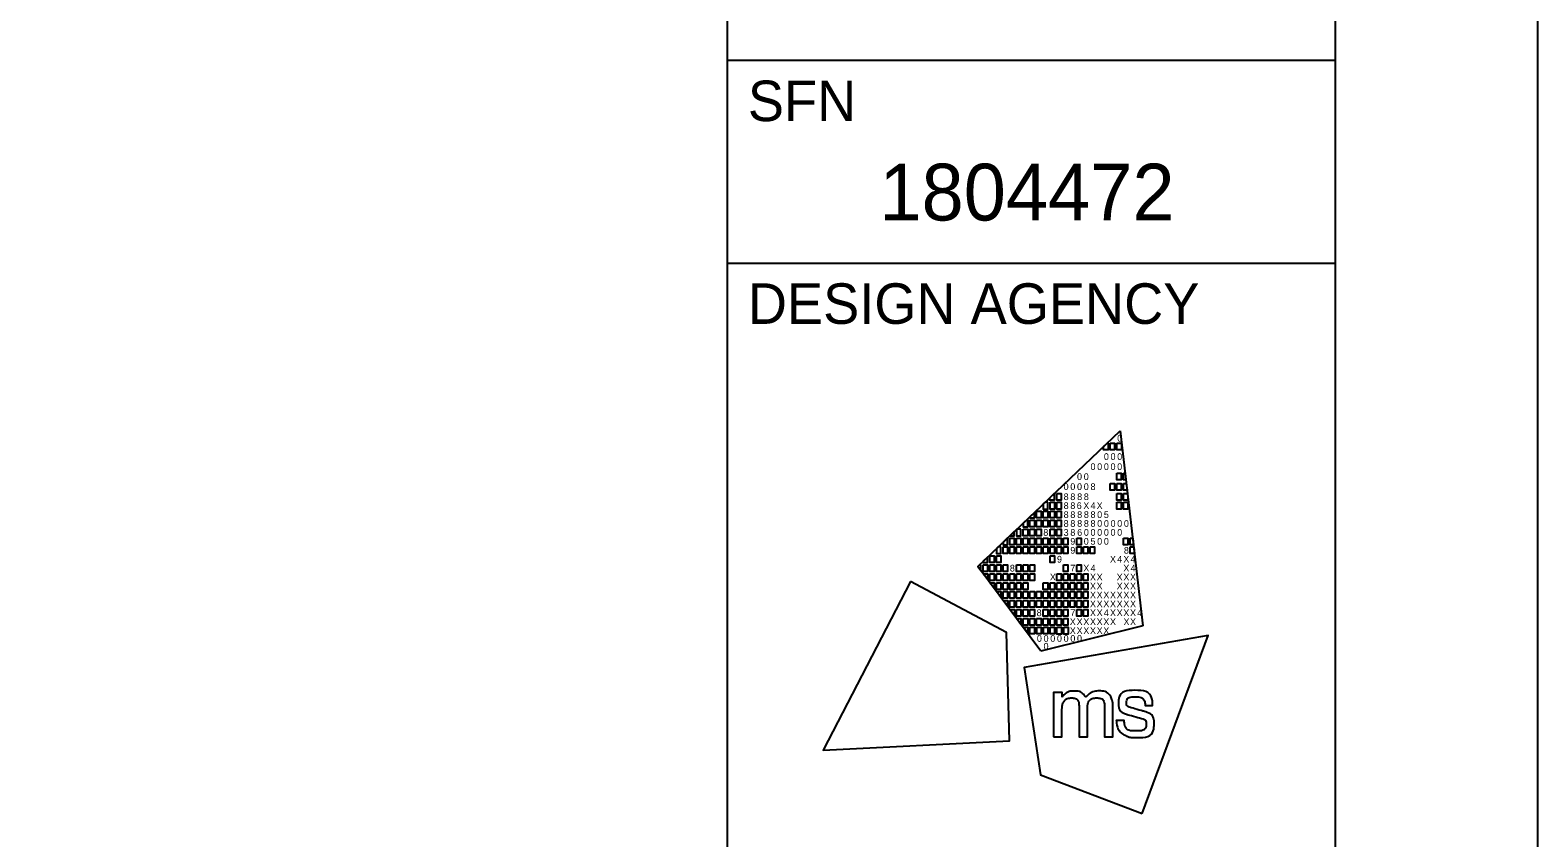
# Model space of a CAD drawing. Extents: x 0 to 34, y 0 to 22.
# Drawn here: x 30.278 to 34, y 3.582 to 5.574 of the extents above; entities that cross this region are included whole.
import ezdxf

# ---------------------------------------------------------------- set-up
doc = ezdxf.new("R2010")
doc.units = 0
for name, color, linetype in [('Default', 7, 'Continuous'), ('SH_Border', 7, 'Continuous'), ('SH_Cut_Line', 7, 'Continuous'), ('SH_Data', 7, 'Continuous')]:
    doc.layers.add(name, color=color, linetype=linetype)

msp = doc.modelspace()

# ---------------------------------------------------------------- linework, layer by layer
at = {"layer": 'Default'}
for p, q in [((32.6176, 4.2519), (32.9688, 4.5861)), ((32.9688, 4.5861), (32.9688, 4.5861)), ((32.9688, 4.5861), (33.0253, 4.1052)), ((32.773, 4.043), (32.6176, 4.2519)), ((33.0253, 4.1052), (32.773, 4.043))]:
    msp.add_line(p, q, dxfattribs=at)
for points in [[(32.9279, 4.5472), (32.9369, 4.5558), (32.939, 4.5558), (32.939, 4.5393), (32.9279, 4.5393)], [(32.9444, 4.5558), (32.9554, 4.5558), (32.9554, 4.5393), (32.9444, 4.5393)], [(32.9609, 4.5558), (32.9719, 4.5558), (32.9719, 4.5393), (32.9609, 4.5393)], [(32.9606, 4.4815), (32.9716, 4.4815), (32.9716, 4.465), (32.9606, 4.465)], [(32.9771, 4.4815), (32.9811, 4.4815), (32.983, 4.465), (32.9771, 4.465)], [(32.7954, 4.4211), (32.8064, 4.4316), (32.8064, 4.4154), (32.7954, 4.4154)], [(32.8123, 4.4319), (32.8233, 4.4319), (32.8233, 4.4154), (32.8123, 4.4154)], [(32.9442, 4.4567), (32.9552, 4.4567), (32.9552, 4.4402), (32.9442, 4.4402)], [(32.9606, 4.4567), (32.9716, 4.4567), (32.9716, 4.4402), (32.9606, 4.4402)], [(32.9606, 4.4319), (32.9716, 4.4319), (32.9716, 4.4154), (32.9606, 4.4154)], [(32.9771, 4.4567), (32.984, 4.4567), (32.9859, 4.4402), (32.9771, 4.4402)], [(32.9771, 4.4319), (32.9869, 4.4319), (32.9881, 4.4218), (32.9881, 4.4154), (32.9771, 4.4154)], [(32.7958, 4.4099), (32.8068, 4.4099), (32.8068, 4.3934), (32.7958, 4.3934)], [(32.8123, 4.4099), (32.8233, 4.4099), (32.8233, 4.3934), (32.8123, 4.3934)], [(32.9606, 4.4099), (32.9716, 4.4099), (32.9716, 4.3934), (32.9606, 4.3934)], [(32.9771, 4.4099), (32.9881, 4.4099), (32.9881, 4.3934), (32.9771, 4.3934)], [(32.7463, 4.3659), (32.7573, 4.3659), (32.7573, 4.3494), (32.7463, 4.3494)], [(32.7628, 4.3879), (32.7738, 4.3879), (32.7738, 4.3714), (32.7628, 4.3714)], [(32.7628, 4.3659), (32.7738, 4.3659), (32.7738, 4.3494), (32.7628, 4.3494)], [(32.7793, 4.3879), (32.7903, 4.3879), (32.7903, 4.3714), (32.7793, 4.3714)], [(32.7793, 4.3659), (32.7903, 4.3659), (32.7903, 4.3494), (32.7793, 4.3494)], [(32.7958, 4.3879), (32.8068, 4.3879), (32.8068, 4.3714), (32.7958, 4.3714)], [(32.7958, 4.3659), (32.8068, 4.3659), (32.8068, 4.3494), (32.7958, 4.3494)], [(32.8123, 4.3879), (32.8233, 4.3879), (32.8233, 4.3714), (32.8123, 4.3714)], [(32.8123, 4.3659), (32.8233, 4.3659), (32.8233, 4.3494), (32.8123, 4.3494)], [(32.6967, 4.3218), (32.7077, 4.3218), (32.7077, 4.3053), (32.6967, 4.3053)], [(32.7132, 4.3218), (32.7242, 4.3218), (32.7242, 4.3053), (32.7132, 4.3053)], [(32.7297, 4.3439), (32.7407, 4.3439), (32.7407, 4.3273), (32.7297, 4.3273)], [(32.7297, 4.3218), (32.7407, 4.3218), (32.7407, 4.3053), (32.7297, 4.3053)], [(32.7463, 4.3439), (32.7573, 4.3439), (32.7573, 4.3273), (32.7463, 4.3273)], [(32.7463, 4.3218), (32.7573, 4.3218), (32.7573, 4.3053), (32.7463, 4.3053)], [(32.7628, 4.3439), (32.7738, 4.3439), (32.7738, 4.3273), (32.7628, 4.3273)], [(32.7628, 4.3218), (32.7738, 4.3218), (32.7738, 4.3053), (32.7628, 4.3053)], [(32.7793, 4.3218), (32.7903, 4.3218), (32.7903, 4.3053), (32.7793, 4.3053)], [(32.7958, 4.3439), (32.8068, 4.3439), (32.8068, 4.3273), (32.7958, 4.3273)], [(32.7958, 4.3218), (32.8068, 4.3218), (32.8068, 4.3053), (32.7958, 4.3053)], [(32.8123, 4.3439), (32.8233, 4.3439), (32.8233, 4.3273), (32.8123, 4.3273)], [(32.8123, 4.3218), (32.8233, 4.3218), (32.8233, 4.3053), (32.8123, 4.3053)], [(32.8288, 4.3218), (32.8398, 4.3218), (32.8398, 4.3053), (32.8288, 4.3053)], [(32.8618, 4.3218), (32.8729, 4.3218), (32.8729, 4.3053), (32.8618, 4.3053)], [(32.9771, 4.3218), (32.9881, 4.3218), (32.9881, 4.3053), (32.9771, 4.3053)], [(32.9936, 4.3218), (32.9999, 4.3218), (33.0018, 4.3053), (32.9936, 4.3053)], [(32.6802, 4.2998), (32.6912, 4.2998), (32.6912, 4.2833), (32.6802, 4.2833)], [(32.6967, 4.2998), (32.7077, 4.2998), (32.7077, 4.2833), (32.6967, 4.2833)], [(32.7132, 4.2998), (32.7242, 4.2998), (32.7242, 4.2833), (32.7132, 4.2833)], [(32.7297, 4.2998), (32.7407, 4.2998), (32.7407, 4.2833), (32.7297, 4.2833)], [(32.7463, 4.2998), (32.7573, 4.2998), (32.7573, 4.2833), (32.7463, 4.2833)], [(32.7628, 4.2998), (32.7738, 4.2998), (32.7738, 4.2833), (32.7628, 4.2833)], [(32.7793, 4.2998), (32.7903, 4.2998), (32.7903, 4.2833), (32.7793, 4.2833)], [(32.7958, 4.2998), (32.8068, 4.2998), (32.8068, 4.2833), (32.7958, 4.2833)], [(32.8123, 4.2998), (32.8233, 4.2998), (32.8233, 4.2833), (32.8123, 4.2833)], [(32.8288, 4.2998), (32.8398, 4.2998), (32.8398, 4.2833), (32.8288, 4.2833)], [(32.8618, 4.2998), (32.8729, 4.2998), (32.8729, 4.2833), (32.8618, 4.2833)], [(32.8784, 4.2998), (32.8894, 4.2998), (32.8894, 4.2833), (32.8784, 4.2833)], [(32.8947, 4.2998), (32.9057, 4.2998), (32.9057, 4.2833), (32.8947, 4.2833)], [(32.9936, 4.2998), (33.0024, 4.2998), (33.0044, 4.2833), (32.9936, 4.2833)], [(32.6307, 4.2558), (32.6417, 4.2558), (32.6417, 4.2393), (32.6307, 4.2393)], [(32.6472, 4.2778), (32.6582, 4.2778), (32.6582, 4.2613), (32.6472, 4.2613)], [(32.6472, 4.2558), (32.6582, 4.2558), (32.6582, 4.2393), (32.6472, 4.2393)], [(32.6637, 4.2778), (32.6747, 4.2778), (32.6747, 4.2613), (32.6637, 4.2613)], [(32.6637, 4.2558), (32.6747, 4.2558), (32.6747, 4.2393), (32.6637, 4.2393)], [(32.6802, 4.2558), (32.6912, 4.2558), (32.6912, 4.2393), (32.6802, 4.2393)], [(32.7132, 4.2558), (32.7242, 4.2558), (32.7242, 4.2393), (32.7132, 4.2393)], [(32.7297, 4.2558), (32.7407, 4.2558), (32.7407, 4.2393), (32.7297, 4.2393)], [(32.7463, 4.2558), (32.7573, 4.2558), (32.7573, 4.2393), (32.7463, 4.2393)], [(32.7958, 4.2778), (32.8068, 4.2778), (32.8068, 4.2613), (32.7958, 4.2613)], [(32.8288, 4.2558), (32.8398, 4.2558), (32.8398, 4.2393), (32.8288, 4.2393)], [(32.8618, 4.2558), (32.8729, 4.2558), (32.8729, 4.2393), (32.8618, 4.2393)], [(32.6307, 4.2338), (32.6417, 4.2338), (32.6417, 4.22)], [(32.6472, 4.2338), (32.6582, 4.2338), (32.6582, 4.2173), (32.6472, 4.2173)], [(32.6472, 4.2117), (32.6582, 4.2117), (32.6582, 4.198)], [(32.6637, 4.2338), (32.6747, 4.2338), (32.6747, 4.2173), (32.6637, 4.2173)], [(32.6637, 4.2117), (32.6747, 4.2117), (32.6747, 4.1952), (32.6637, 4.1952)], [(32.6802, 4.2338), (32.6912, 4.2338), (32.6912, 4.2173), (32.6802, 4.2173)], [(32.6802, 4.2117), (32.6912, 4.2117), (32.6912, 4.1952), (32.6802, 4.1952)], [(32.6967, 4.2338), (32.7077, 4.2338), (32.7077, 4.2173), (32.6967, 4.2173)], [(32.6967, 4.2117), (32.7077, 4.2117), (32.7077, 4.1952), (32.6967, 4.1952)], [(32.7132, 4.2338), (32.7242, 4.2338), (32.7242, 4.2173), (32.7132, 4.2173)], [(32.7132, 4.2117), (32.7242, 4.2117), (32.7242, 4.1952), (32.7132, 4.1952)], [(32.7297, 4.2338), (32.7407, 4.2338), (32.7407, 4.2173), (32.7297, 4.2173)], [(32.7297, 4.2117), (32.7407, 4.2117), (32.7407, 4.1952), (32.7297, 4.1952)], [(32.7463, 4.2338), (32.7573, 4.2338), (32.7573, 4.2173), (32.7463, 4.2173)], [(32.7793, 4.2117), (32.7903, 4.2117), (32.7903, 4.1952), (32.7793, 4.1952)], [(32.7958, 4.2117), (32.8068, 4.2117), (32.8068, 4.1952), (32.7958, 4.1952)], [(32.8123, 4.2338), (32.8233, 4.2338), (32.8233, 4.2173), (32.8123, 4.2173)], [(32.8123, 4.2117), (32.8233, 4.2117), (32.8233, 4.1952), (32.8123, 4.1952)], [(32.8288, 4.2338), (32.8398, 4.2338), (32.8398, 4.2173), (32.8288, 4.2173)], [(32.8288, 4.2117), (32.8398, 4.2117), (32.8398, 4.1952), (32.8288, 4.1952)], [(32.8453, 4.2338), (32.8563, 4.2338), (32.8563, 4.2173), (32.8453, 4.2173)], [(32.8453, 4.2117), (32.8563, 4.2117), (32.8563, 4.1952), (32.8453, 4.1952)], [(32.8618, 4.2338), (32.8729, 4.2338), (32.8729, 4.2173), (32.8618, 4.2173)], [(32.8618, 4.2117), (32.8729, 4.2117), (32.8729, 4.1952), (32.8618, 4.1952)], [(32.8784, 4.2338), (32.8894, 4.2338), (32.8894, 4.2173), (32.8784, 4.2173)], [(32.8784, 4.2117), (32.8894, 4.2117), (32.8894, 4.1952), (32.8784, 4.1952)], [(32.6637, 4.1897), (32.6747, 4.1897), (32.6747, 4.176)], [(32.6747, 4.1897), (32.6747, 4.1897), (32.6747, 4.1897)], [(32.6802, 4.1897), (32.6912, 4.1897), (32.6912, 4.1732), (32.6802, 4.1732)], [(32.6967, 4.1897), (32.7077, 4.1897), (32.7077, 4.1732), (32.6967, 4.1732)], [(32.7132, 4.1897), (32.7242, 4.1897), (32.7242, 4.1732), (32.7132, 4.1732)], [(32.7297, 4.1897), (32.7407, 4.1897), (32.7407, 4.1732), (32.7297, 4.1732)], [(32.7463, 4.1897), (32.7573, 4.1897), (32.7573, 4.1732), (32.7463, 4.1732)], [(32.7628, 4.1897), (32.7738, 4.1897), (32.7738, 4.1732), (32.7628, 4.1732)], [(32.7793, 4.1897), (32.7903, 4.1897), (32.7903, 4.1732), (32.7793, 4.1732)], [(32.7958, 4.1897), (32.8068, 4.1897), (32.8068, 4.1732), (32.7958, 4.1732)], [(32.8123, 4.1897), (32.8233, 4.1897), (32.8233, 4.1732), (32.8123, 4.1732)], [(32.8288, 4.1897), (32.8398, 4.1897), (32.8398, 4.1732), (32.8288, 4.1732)], [(32.8453, 4.1897), (32.8563, 4.1897), (32.8563, 4.1732), (32.8453, 4.1732)], [(32.8618, 4.1897), (32.8729, 4.1897), (32.8729, 4.1732), (32.8618, 4.1732)], [(32.8784, 4.1897), (32.8894, 4.1897), (32.8894, 4.1732), (32.8784, 4.1732)], [(32.6802, 4.1677), (32.6912, 4.1677), (32.6912, 4.154)], [(32.7078, 4.1305), (32.6966, 4.1457), (32.7078, 4.1457)], [(32.6967, 4.1677), (32.7077, 4.1677), (32.7077, 4.1512), (32.6967, 4.1512)], [(32.7132, 4.1677), (32.7242, 4.1677), (32.7242, 4.1512), (32.7132, 4.1512)], [(32.7132, 4.1457), (32.7242, 4.1457), (32.7242, 4.1292), (32.7132, 4.1292)], [(32.7297, 4.1677), (32.7407, 4.1677), (32.7407, 4.1512), (32.7297, 4.1512)], [(32.7297, 4.1457), (32.7407, 4.1457), (32.7407, 4.1292), (32.7297, 4.1292)], [(32.7463, 4.1677), (32.7573, 4.1677), (32.7573, 4.1512), (32.7463, 4.1512)], [(32.7463, 4.1457), (32.7573, 4.1457), (32.7573, 4.1292), (32.7463, 4.1292)], [(32.7628, 4.1677), (32.7738, 4.1677), (32.7738, 4.1512), (32.7628, 4.1512)], [(32.7793, 4.1677), (32.7903, 4.1677), (32.7903, 4.1512), (32.7793, 4.1512)], [(32.7793, 4.1457), (32.7903, 4.1457), (32.7903, 4.1292), (32.7793, 4.1292)], [(32.7958, 4.1677), (32.8068, 4.1677), (32.8068, 4.1512), (32.7958, 4.1512)], [(32.7958, 4.1457), (32.8068, 4.1457), (32.8068, 4.1292), (32.7958, 4.1292)], [(32.8123, 4.1677), (32.8233, 4.1677), (32.8233, 4.1512), (32.8123, 4.1512)], [(32.8123, 4.1457), (32.8233, 4.1457), (32.8233, 4.1292), (32.8123, 4.1292)], [(32.8288, 4.1677), (32.8398, 4.1677), (32.8398, 4.1512), (32.8288, 4.1512)], [(32.8288, 4.1457), (32.8398, 4.1457), (32.8398, 4.1292), (32.8288, 4.1292)], [(32.8453, 4.1677), (32.8563, 4.1677), (32.8563, 4.1512), (32.8453, 4.1512)], [(32.8618, 4.1677), (32.8729, 4.1677), (32.8729, 4.1512), (32.8618, 4.1512)], [(32.8618, 4.1457), (32.8729, 4.1457), (32.8729, 4.1292), (32.8618, 4.1292)], [(32.8784, 4.1677), (32.8894, 4.1677), (32.8894, 4.1512), (32.8784, 4.1512)], [(32.8784, 4.1457), (32.8894, 4.1457), (32.8894, 4.1292), (32.8784, 4.1292)], [(32.724, 4.1082), (32.7132, 4.1237), (32.7242, 4.1237)], [(32.7297, 4.1237), (32.7407, 4.1237), (32.7407, 4.1072), (32.7297, 4.1072)], [(32.7302, 4.1017), (32.7407, 4.1017), (32.7408, 4.0875)], [(32.7463, 4.1237), (32.7573, 4.1237), (32.7573, 4.1072), (32.7463, 4.1072)], [(32.7463, 4.1017), (32.7573, 4.1017), (32.7573, 4.0852), (32.7463, 4.0852)], [(32.7628, 4.1237), (32.7738, 4.1237), (32.7738, 4.1072), (32.7628, 4.1072)], [(32.763, 4.1017), (32.774, 4.1017), (32.774, 4.0852), (32.763, 4.0852)], [(32.7793, 4.1237), (32.7903, 4.1237), (32.7903, 4.1072), (32.7793, 4.1072)], [(32.7794, 4.1017), (32.7904, 4.1017), (32.7904, 4.0852), (32.7794, 4.0852)], [(32.7958, 4.1237), (32.8068, 4.1237), (32.8068, 4.1072), (32.7958, 4.1072)], [(32.7961, 4.1017), (32.8071, 4.1017), (32.8071, 4.0852), (32.7961, 4.0852)], [(32.8123, 4.1237), (32.8233, 4.1237), (32.8233, 4.1072), (32.8123, 4.1072)], [(32.813, 4.1017), (32.824, 4.1017), (32.824, 4.0851), (32.813, 4.0851)], [(32.8288, 4.1237), (32.8398, 4.1237), (32.8398, 4.1072), (32.8288, 4.1072)], [(32.8296, 4.1017), (32.8407, 4.1017), (32.8407, 4.0851), (32.8296, 4.0851)]]:
    msp.add_lwpolyline(points, close=True, dxfattribs=at)
for points in [[(32.7903, 4.4099), (32.7836, 4.4099), (32.7793, 4.4058), (32.7793, 4.3934), (32.7903, 4.3934), (32.7903, 4.4099)], [(32.7407, 4.3691), (32.7297, 4.3587), (32.7297, 4.3494), (32.7407, 4.3494), (32.7407, 4.3691)], [(32.7573, 4.3849), (32.7463, 4.3744), (32.7463, 4.3714), (32.7573, 4.3714), (32.7573, 4.3849)], [(32.6912, 4.322), (32.6802, 4.3115), (32.6802, 4.3053), (32.6912, 4.3053), (32.6912, 4.322)], [(32.7077, 4.3377), (32.6968, 4.3273), (32.7077, 4.3273), (32.7077, 4.3377)], [(32.7242, 4.3439), (32.7142, 4.3439), (32.7132, 4.343), (32.7132, 4.3273), (32.7242, 4.3273), (32.7242, 4.3439)], [(32.6747, 4.2998), (32.6679, 4.2998), (32.6637, 4.2958), (32.6637, 4.2833), (32.6747, 4.2833), (32.6747, 4.2998)], [(32.6252, 4.2558), (32.6216, 4.2558), (32.6176, 4.2519), (32.6252, 4.2417), (32.6252, 4.2558)], [(32.6417, 4.2749), (32.6307, 4.2644), (32.6307, 4.2613), (32.6417, 4.2613), (32.6417, 4.2749)], [(32.4512, 4.2149), (32.2359, 3.7988), (32.6957, 3.8215), (32.6884, 4.0892), (32.4512, 4.2149)], [(33.0229, 3.6422), (33.1859, 4.0814), (32.7324, 4.0029), (32.7722, 3.7381), (33.0229, 3.6422)]]:
    msp.add_lwpolyline(points, dxfattribs=at)
for points in [[(32.9596, 3.8709), (32.9596, 3.8709), (32.9595, 3.8717), (32.9595, 3.8717), (32.9595, 3.8717), (32.9603, 3.8717), (32.9603, 3.8717), (32.9603, 3.8717), (32.9783, 3.8717), (32.9783, 3.8717), (32.9783, 3.8717), (32.9789, 3.8717), (32.9789, 3.8717), (32.9789, 3.8717), (32.979, 3.871), (32.979, 3.871), (32.9803, 3.8554), (32.9887, 3.846), (33.009, 3.846), (33.0273, 3.846), (33.0333, 3.8554), (33.0333, 3.8631), (33.0333, 3.8732), (33.0256, 3.8758), (33.0175, 3.878), (33.0175, 3.878), (32.987, 3.8867), (32.987, 3.8867), (32.9721, 3.8909), (32.9648, 3.9019), (32.9648, 3.9142), (32.9648, 3.9303), (32.9768, 3.9462), (33.0052, 3.9462), (33.0348, 3.9462), (33.0489, 3.9285), (33.0489, 3.9095), (33.0489, 3.9095), (33.0489, 3.9087), (33.0489, 3.9087), (33.0489, 3.9087), (33.0482, 3.9087), (33.0482, 3.9087), (33.0482, 3.9087), (33.0312, 3.9087), (33.0312, 3.9087), (33.0312, 3.9087), (33.0305, 3.9087), (33.0305, 3.9087), (33.0305, 3.9087), (33.0305, 3.9094), (33.0305, 3.9094), (33.0302, 3.9208), (33.0227, 3.93), (33.0056, 3.93), (32.9891, 3.93), (32.9843, 3.9218), (32.9843, 3.9157), (32.9843, 3.9108), (32.9869, 3.9059), (32.9959, 3.9033), (32.9959, 3.9033), (33.0255, 3.8948), (33.0255, 3.8948), (33.0462, 3.8889), (33.0527, 3.8777), (33.0527, 3.8639), (33.0527, 3.8462), (33.041, 3.8298), (33.0087, 3.8298), (32.9952, 3.8298), (32.9877, 3.8321), (32.9823, 3.8348), (32.9691, 3.8414), (32.961, 3.8536), (32.9596, 3.8709)], [(32.8048, 3.8315), (32.8048, 3.8315), (32.8048, 3.9409), (32.8048, 3.9409), (32.8048, 3.9409), (32.8255, 3.9409), (32.8255, 3.9409), (32.8255, 3.9409), (32.8255, 3.9297), (32.8255, 3.9297), (32.8346, 3.9399), (32.8457, 3.9445), (32.8555, 3.9445), (32.8689, 3.9445), (32.8792, 3.9372), (32.8837, 3.9266), (32.8915, 3.9381), (32.905, 3.9446), (32.9166, 3.9446), (32.9325, 3.9446), (32.9451, 3.935), (32.9494, 3.9213), (32.9494, 3.9212), (32.9494, 3.9212), (32.9495, 3.9212), (32.9501, 3.919), (32.9507, 3.9172), (32.9507, 3.9071), (32.9507, 3.9071), (32.9507, 3.8314), (32.9507, 3.8314), (32.9507, 3.8314), (32.9303, 3.8314), (32.9303, 3.8314), (32.9303, 3.8314), (32.9303, 3.9048), (32.9303, 3.9048), (32.9303, 3.9201), (32.9219, 3.9274), (32.9111, 3.9274), (32.8995, 3.9274), (32.888, 3.9171), (32.888, 3.9001), (32.888, 3.9001), (32.888, 3.8315), (32.888, 3.8315), (32.888, 3.8315), (32.8674, 3.8315), (32.8674, 3.8315), (32.8674, 3.8315), (32.8674, 3.9059), (32.8674, 3.9059), (32.8674, 3.9203), (32.8588, 3.9274), (32.8497, 3.9274), (32.8384, 3.9274), (32.8254, 3.917), (32.8254, 3.8962), (32.8254, 3.8962), (32.8254, 3.8315), (32.8254, 3.8315), (32.8254, 3.8315), (32.8048, 3.8315), (32.8048, 3.8315)]]:
    msp.add_open_spline(points, degree=3, dxfattribs=at)
at = {"layer": 'SH_Border'}
for p, q in [((32, 0.5), (32, 21.5)), ((32, 5.5), (33.5, 5.5)), ((32, 5), (33.5, 5))]:
    msp.add_line(p, q, dxfattribs=at)
msp.add_lwpolyline([(1.5, 21.5), (33.5, 21.5), (33.5, 0.5), (1.5, 0.5)], close=True, dxfattribs=at)
at = {"layer": 'SH_Cut_Line'}
msp.add_lwpolyline([(0, 0), (34, 0), (34, 22), (0, 22)], close=True, dxfattribs=at)
at = {"layer": 'SH_Data'}
msp.add_line((32.75, 4), (32.75, 4), dxfattribs=at)

# ---------------------------------------------------------------- texts
at = {"layer": 'Default'}
for s, p in [('0', (32.9617, 4.5597)), ('0', (32.8958, 4.4897)), ('0', (32.9123, 4.4897)), ('0', (32.9288, 4.5145)), ('0', (32.9288, 4.4897)), ('0', (32.9453, 4.5145)), ('0', (32.9453, 4.4897)), ('0', (32.9617, 4.5145)), ('0', (32.9617, 4.4897)), ('0', (32.8625, 4.465)), ('0', (32.8791, 4.465)), ('0', (32.8295, 4.4402)), ('8', (32.8295, 4.4154)), ('0', (32.846, 4.4402)), ('8', (32.846, 4.4154)), ('0', (32.8625, 4.4402)), ('8', (32.8629, 4.4154)), ('0', (32.8791, 4.4402)), ('8', (32.8793, 4.4154)), ('8', (32.8958, 4.4402)), ('8', (32.8295, 4.3934)), ('8', (32.846, 4.3934)), ('6', (32.8618, 4.3934)), ('X', (32.8781, 4.3934)), ('4', (32.8959, 4.3934)), ('X', (32.911, 4.3934)), ('8', (32.8295, 4.3713)), ('8', (32.8295, 4.3494)), ('8', (32.846, 4.3713)), ('8', (32.846, 4.3494)), ('8', (32.8629, 4.3713)), ('8', (32.8629, 4.3494)), ('8', (32.8794, 4.3713)), ('8', (32.8794, 4.3494)), ('8', (32.8958, 4.3713)), ('8', (32.8958, 4.3494)), ('0', (32.9123, 4.3713)), ('0', (32.9123, 4.3494)), ('5', (32.9287, 4.3713)), ('0', (32.9288, 4.3494)), ('0', (32.9453, 4.3494)), ('0', (32.9617, 4.3494)), ('0', (32.9782, 4.3494)), ('8', (32.7793, 4.3273)), ('3', (32.8295, 4.3273)), ('8', (32.846, 4.3273)), ('9', (32.846, 4.3053)), ('6', (32.8629, 4.3273)), ('0', (32.8791, 4.3053)), ('0', (32.8794, 4.3273)), ('0', (32.8958, 4.3273)), ('5', (32.8958, 4.3053)), ('0', (32.9123, 4.3273)), ('0', (32.9123, 4.3053)), ('0', (32.9288, 4.3273)), ('0', (32.9288, 4.3053)), ('0', (32.9453, 4.3273)), ('0', (32.9617, 4.3273)), ('9', (32.846, 4.2833)), ('8', (32.9782, 4.2833)), ('8', (32.6967, 4.2393)), ('9', (32.813, 4.2613)), ('7', (32.846, 4.2393)), ('X', (32.8781, 4.2393)), ('4', (32.8959, 4.2393)), ('X', (32.9439, 4.2613)), ('4', (32.9617, 4.2613)), ('X', (32.9769, 4.2613)), ('X', (32.9769, 4.2393)), ('4', (32.9947, 4.2613)), ('4', (32.9947, 4.2393)), ('X', (32.7955, 4.2173)), ('X', (32.8945, 4.2173)), ('X', (32.8945, 4.1952)), ('X', (32.911, 4.2173)), ('X', (32.911, 4.1952)), ('X', (32.9604, 4.2173)), ('X', (32.9604, 4.1952)), ('X', (32.9769, 4.2173)), ('X', (32.9769, 4.1952)), ('X', (32.9934, 4.2173)), ('X', (32.9934, 4.1952)), ('X', (32.8945, 4.1732)), ('X', (32.911, 4.1732)), ('X', (32.9275, 4.1732)), ('X', (32.9439, 4.1732)), ('X', (32.9604, 4.1732)), ('X', (32.9769, 4.1732)), ('X', (32.9934, 4.1732)), ('8', (32.7628, 4.1292)), ('7', (32.846, 4.1292)), ('X', (32.8945, 4.1512)), ('X', (32.8945, 4.1292)), ('X', (32.911, 4.1512)), ('X', (32.911, 4.1292)), ('X', (32.9275, 4.1512)), ('4', (32.9288, 4.1292)), ('X', (32.9439, 4.1512)), ('X', (32.9439, 4.1292)), ('X', (32.9604, 4.1512)), ('X', (32.9604, 4.1292)), ('X', (32.9769, 4.1512)), ('X', (32.9769, 4.1292)), ('X', (32.9934, 4.1512)), ('X', (32.9934, 4.1292)), ('4', (33.0112, 4.1292)), ('X', (32.8447, 4.1072)), ('X', (32.8447, 4.0851)), ('X', (32.8616, 4.1072)), ('X', (32.8616, 4.0851)), ('X', (32.8781, 4.1072)), ('X', (32.8781, 4.0851)), ('X', (32.8945, 4.1072)), ('X', (32.8945, 4.0851)), ('X', (32.911, 4.1072)), ('X', (32.911, 4.0851)), ('X', (32.9275, 4.1072)), ('X', (32.9275, 4.0851)), ('X', (32.9439, 4.1072)), ('X', (32.9772, 4.1072)), ('X', (32.9934, 4.1072)), ('0', (32.7635, 4.0659)), ('0', (32.78, 4.0659)), ('0', (32.78, 4.0467)), ('0', (32.7965, 4.0659)), ('0', (32.813, 4.0659)), ('0', (32.8295, 4.0659)), ('0', (32.846, 4.0659)), ('0', (32.8625, 4.0659))]:
    msp.add_text(s, height=0.0165, rotation=360, dxfattribs=at).set_placement(p)
at = {"layer": 'SH_Data'}
for s, height, p in [('SFN', 0.1, (32.05, 5.35)), ('1804472', 0.14, (32.3746, 5.105)), ('DESIGN AGENCY', 0.1, (32.05, 4.85))]:
    msp.add_text(s, height=height, dxfattribs=at).set_placement(p)

doc.saveas('drawing.dxf')
